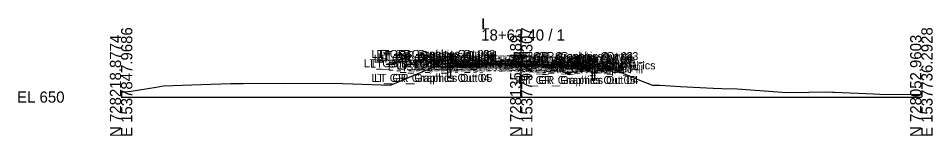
# Model space of a CAD drawing. Extents: x -26 to 1203, y -10 to 9522.
# Drawn here: x 974.3 to 1202.8, y -9.7 to 19.7 of the extents above; entities that cross this region are included whole.
import ezdxf

# ---------------------------------------------------------------- set-up
doc = ezdxf.new("R2010")
doc.units = 0
for name, color, linetype in [('Default', 7, 'Continuous'), ('Exist CMT Pavement', 7, 'Continuous'), ('Exist Cross Section Cell', 7, 'Continuous'), ('Exist XS Center Line Elevation Label', 7, 'Continuous'), ('Exist XS Ground Line', 7, 'Continuous'), ('Old_Level_63', 7, 'Continuous'), ('Prop CMT Guardrail Graphics', 7, 'Continuous'), ('Prop CMT Pvmt Course 1', 7, 'Continuous'), ('Prop CMT Pvmt Course 1 Wedge', 7, 'Continuous'), ('Prop CMT Pvmt Course 2 Wedge', 7, 'Continuous'), ('Prop CMT Pvmt Course 3', 7, 'Continuous'), ('Prop CMT Pvmt Surface', 7, 'Continuous'), ('Prop CMT Pvmt Surface Shoulder', 7, 'Continuous'), ('Prop CMT Pvmt Wedge Surface 1', 7, 'Continuous'), ('Prop CMT Pvmt Wedge Surface 2', 7, 'Continuous'), ('Prop CMT Pvmt Wedge Surface 3', 7, 'Continuous'), ('Prop CMT Shld Paved Course 1', 7, 'Continuous'), ('Prop CMT Shld Paved Course 2', 7, 'Continuous'), ('Prop CMT Shld Paved Course 3', 7, 'Continuous'), ('Prop CMT Slope Grass', 7, 'Continuous'), ('Prop CMT Subgrade Earthwork', 7, 'Continuous'), ('Prop Superelevation  Arrow CELL', 7, 'Continuous'), ('Prop XS EOT Tick Mark', 7, 'Continuous'), ('Prop XS SE Text', 7, 'Continuous'), ('Prop XS Side Slope Text', 7, 'Continuous')]:
    doc.layers.add(name, color=color, linetype=linetype)

msp = doc.modelspace()

# ---------------------------------------------------------------- linework, layer by layer
at = {"layer": 'Exist CMT Pavement'}
for points in [[(1100, 8.04), (1098.83, 8.04), (1094.75, 8.04), (1091.6, 8.04), (1090.66, 8.06), (1089.49, 8.08)], [(1100, 8.04), (1101.06, 8.04), (1101.22, 8.04), (1105.5, 7.93), (1109.35, 7.83), (1109.78, 7.82), (1111, 7.78)]]:
    msp.add_lwpolyline(points, dxfattribs=at)
at = {"layer": 'Exist Cross Section Cell'}
for p, q in [((1100, 0), (1100, 16.95)), ((1000, 0), (1100, 0)), ((1100, 0), (1200, 0))]:
    msp.add_line(p, q, dxfattribs=at)
at = {"layer": 'Exist XS Ground Line'}
msp.add_lwpolyline([(1000, 1.2), (1002.51, 1.52), (1008.74, 2.49), (1010.57, 2.78), (1022.45, 3.22), (1027.4, 3.4), (1030.47, 3.42), (1040.87, 3.48), (1055.34, 3.4), (1057.95, 3.32), (1067.32, 3), (1077.83, 7.38), (1078.04, 7.48), (1078.32, 7.5), (1087.4, 8.11), (1091.6, 8.04), (1100, 8.04), (1101.06, 8.04), (1109.35, 7.83), (1113.37, 7.7), (1117.2, 7.4), (1123.14, 6.93), (1130.37, 3.94), (1132.85, 3), (1134.61, 2.99), (1139.79, 2.62), (1147.95, 2.24), (1150.15, 2.14), (1153.93, 2.09), (1166.42, 1.14), (1177.39, 1.27), (1177.81, 1.25), (1178.25, 1.24), (1188.02, 0.82), (1189.59, 0.76), (1197.53, 0.67), (1200, 0.65)], dxfattribs=at)
at = {"layer": 'Prop CMT Guardrail Graphics'}
for points in [[(1081.63, 4.8), (1081.63, 10.8)], [(1081.63, 10.8), (1082.97, 10.8), (1083.24, 10.51)], [(1083.24, 9.93), (1082.97, 9.64), (1082.3, 9.64)], [(1082.3, 9.64), (1082.3, 4.8)], [(1083.24, 10.51), (1082.97, 10.22)], [(1082.97, 10.22), (1083.24, 9.93)], [(1118.37, 10.27), (1117.03, 10.27), (1116.76, 9.98)], [(1116.76, 9.98), (1117.03, 9.69)], [(1117.03, 9.69), (1116.76, 9.4)], [(1116.76, 9.4), (1117.03, 9.11), (1117.7, 9.11)], [(1118.37, 4.27), (1118.37, 10.27)], [(1117.7, 9.11), (1117.7, 4.27)], [(1082.3, 4.8), (1081.63, 4.8)], [(1117.7, 4.27), (1118.37, 4.27)]]:
    msp.add_lwpolyline(points, dxfattribs=at)
at = {"layer": 'Prop CMT Pvmt Course 1'}
for points in [[(1100, 8.37), (1089.49, 8.43)], [(1089.49, 8.43), (1089.49, 8.18), (1089.49, 8.18), (1089.49, 8.18)], [(1089.49, 8.18), (1100, 8.12)], [(1100, 8.12), (1100, 8.37)], [(1100, 8.37), (1111, 8.09)], [(1100, 8.12), (1100, 8.37)], [(1111, 7.84), (1100, 8.12)], [(1111, 8.09), (1111, 7.84), (1111, 7.84), (1111, 7.84)]]:
    msp.add_lwpolyline(points, dxfattribs=at)
at = {"layer": 'Prop CMT Pvmt Course 1 Wedge'}
for points in [[(1089.49, 8.18), (1091.6, 8.17), (1100, 8.12)], [(1089.49, 8.08), (1089.49, 8.18)], [(1100, 8.04), (1091.6, 8.04), (1089.49, 8.08)], [(1100, 8.12), (1100, 8.04)], [(1100, 8.12), (1101.06, 8.09), (1109.35, 7.88), (1111, 7.84)], [(1100, 8.04), (1100, 8.12)], [(1111, 7.78), (1109.35, 7.83), (1101.06, 8.04), (1100, 8.04)], [(1111, 7.84), (1111, 7.78)]]:
    msp.add_lwpolyline(points, dxfattribs=at)
at = {"layer": 'Prop CMT Pvmt Course 2 Wedge'}
for points in [[(1089.49, 8.18), (1091.6, 8.17), (1100, 8.12)], [(1089.49, 8.08), (1089.49, 8.18)], [(1100, 8.04), (1091.6, 8.04), (1089.49, 8.08)], [(1100, 8.12), (1100, 8.04)], [(1100, 8.12), (1101.06, 8.09), (1109.35, 7.88), (1111, 7.84)], [(1100, 8.04), (1100, 8.12)], [(1111, 7.78), (1109.35, 7.83), (1101.06, 8.04), (1100, 8.04)], [(1111, 7.84), (1111, 7.78)]]:
    msp.add_lwpolyline(points, dxfattribs=at)
at = {"layer": 'Prop CMT Pvmt Course 3'}
for points in [[(1089.49, 7.97), (1089.49, 7.97), (1089.49, 7.6), (1089.49, 7.6)], [(1089.49, 7.6), (1089.49, 7.97)], [(1111, 7.63), (1111, 7.63), (1111, 7.25), (1111, 7.25)], [(1111, 7.25), (1111, 7.63)]]:
    msp.add_lwpolyline(points, dxfattribs=at)
at = {"layer": 'Prop CMT Pvmt Surface'}
for points in [[(1100, 8.37), (1089.49, 8.43)], [(1100, 8.37), (1111, 8.09)]]:
    msp.add_lwpolyline(points, dxfattribs=at)
at = {"layer": 'Prop CMT Pvmt Surface Shoulder'}
for points in [[(1089.49, 8.43), (1083.25, 8.47)], [(1111, 8.09), (1116.75, 7.94)]]:
    msp.add_lwpolyline(points, dxfattribs=at)
at = {"layer": 'Prop CMT Pvmt Wedge Surface 1'}
for points in [[(1089.49, 8.18), (1089.49, 8.43)], [(1089.49, 8.43), (1089.49, 8.43)], [(1100, 8.12), (1089.49, 8.18)], [(1100, 8.12), (1111, 7.84)], [(1111, 7.84), (1111, 8.09)], [(1111, 8.09), (1111, 8.09)]]:
    msp.add_lwpolyline(points, dxfattribs=at)
at = {"layer": 'Prop CMT Pvmt Wedge Surface 2'}
for points in [[(1089.49, 8.18), (1089.49, 8.43)], [(1100, 8.12), (1089.49, 8.18)], [(1089.49, 8.18), (1089.49, 8.18)], [(1100, 8.12), (1111, 7.84)], [(1111, 7.84), (1111, 8.09)], [(1111, 7.84), (1111, 7.84)]]:
    msp.add_lwpolyline(points, dxfattribs=at)
at = {"layer": 'Prop CMT Pvmt Wedge Surface 3'}
for points in [[(1089.49, 7.97), (1089.49, 8.43)], [(1100, 7.91), (1089.49, 7.97)], [(1089.49, 7.97), (1089.49, 7.97)], [(1100, 7.91), (1111, 7.63)], [(1111, 7.63), (1111, 8.09)], [(1111, 7.63), (1111, 7.63)]]:
    msp.add_lwpolyline(points, dxfattribs=at)
at = {"layer": 'Prop CMT Shld Paved Course 1'}
for points in [[(1089.49, 8.43), (1083.25, 8.47), (1083, 8.22)], [(1083, 8.22), (1089.49, 8.18)], [(1089.49, 8.18), (1089.49, 8.43)], [(1111, 8.09), (1116.75, 7.94), (1117.01, 7.69)], [(1111, 7.84), (1111, 8.09)], [(1117.01, 7.69), (1111, 7.84)]]:
    msp.add_lwpolyline(points, dxfattribs=at)
at = {"layer": 'Prop CMT Shld Paved Course 2'}
for points in [[(1089.49, 8.18), (1083, 8.22), (1082.79, 8.01)], [(1082.79, 8.01), (1089.49, 7.97)], [(1089.49, 7.97), (1089.49, 8.18)], [(1111, 7.84), (1117.01, 7.69), (1117.22, 7.47)], [(1111, 7.63), (1111, 7.84)], [(1117.22, 7.47), (1111, 7.63)]]:
    msp.add_lwpolyline(points, dxfattribs=at)
at = {"layer": 'Prop CMT Shld Paved Course 3'}
for points in [[(1082.79, 8.01), (1082.42, 7.64)], [(1082.42, 7.64), (1089.49, 7.6)], [(1089.49, 7.97), (1082.79, 8.01)], [(1082.79, 8.01), (1082.79, 8.01)], [(1089.49, 7.6), (1089.49, 7.97)], [(1111, 7.63), (1117.22, 7.47)], [(1111, 7.25), (1111, 7.63)], [(1117.61, 7.09), (1111, 7.25)], [(1117.22, 7.47), (1117.22, 7.47)], [(1117.22, 7.47), (1117.61, 7.09)]]:
    msp.add_lwpolyline(points, dxfattribs=at)
at = {"layer": 'Prop CMT Slope Grass'}
for points in [[(1080.58, 8.33), (1078.04, 7.48)], [(1083.24, 8.47), (1080.58, 8.33)], [(1083.25, 8.47), (1083.24, 8.47)], [(1116.75, 7.94), (1116.76, 7.94)], [(1116.76, 7.94), (1119.42, 7.73)], [(1119.42, 7.73), (1123.14, 6.93)]]:
    msp.add_lwpolyline(points, dxfattribs=at)
at = {"layer": 'Prop CMT Subgrade Earthwork'}
for points in [[(1082.42, 7.64), (1081.67, 8.38)], [(1089.49, 7.6), (1082.42, 7.64)], [(1089.49, 7.6), (1089.49, 8.08)], [(1089.49, 7.6), (1089.49, 7.6)], [(1111, 7.25), (1111, 7.78)], [(1111, 7.25), (1117.61, 7.09)], [(1111, 7.25), (1111, 7.25)], [(1117.61, 7.09), (1118.33, 7.82)]]:
    msp.add_lwpolyline(points, dxfattribs=at)
at = {"layer": 'Prop Superelevation  Arrow CELL'}
for p, q in [((1092.29, 9.12), (1098.29, 9)), ((1103.22, 8.9), (1109.22, 8.78))]:
    msp.add_line(p, q, dxfattribs=at)
for points in [[(1098.29, 9), (1096.8, 9.53), (1097.13, 9.02)], [(1109.22, 8.78), (1107.73, 9.31), (1108.07, 8.8)]]:
    msp.add_lwpolyline(points, close=True, dxfattribs=at)
at = {"layer": 'Prop XS EOT Tick Mark'}
for points in [[(1089.49, 8.43), (1089.49, 9.43)], [(1111, 8.09), (1111, 9.09)]]:
    msp.add_lwpolyline(points, dxfattribs=at)

# ---------------------------------------------------------------- texts
at = {"layer": 'Default'}
msp.add_text('-', height=0.0001, dxfattribs=at).set_placement((1000, 0))
msp.add_text('-', height=0.0001, dxfattribs=at).set_placement((1000, 0))
msp.add_text('-', height=0.0001, dxfattribs=at).set_placement((1000, 0))
at = {"layer": 'Exist Cross Section Cell'}
for s, p in [('L', (1090, 16.95)), ('18+63.40 / 1', (1090, 14.15)), ('EL 650', (974, -1.4))]:
    msp.add_text(s, height=2.8, dxfattribs=at).set_placement(p)
for s, p in [('E 1537847.9686', (1002.8, -10)), ('E 1537792.1307', (1102.8, -10)), ('E 1537736.2928', (1202.8, -10)), ('N 728218.8774', (1000, -10)), ('N 728135.9189', (1100, -10)), ('N 728052.9603', (1200, -10))]:
    msp.add_text(s, height=2.8, rotation=90, dxfattribs=at).set_placement(p)
at = {"layer": 'Exist XS Center Line Elevation Label'}
msp.add_text('658.04', height=0.75, dxfattribs=at).set_placement((1098.51, 6.89))
at = {"layer": 'Old_Level_63'}
for s, p in [('LT_GR_Graphics Out 03', (1062.53, 9.8)), ('LT_GR_Graphics Out 02', (1063.86, 9.8)), ('LT_GR_Graphics Out 01', (1064.7, 9.51)), ('LT_GS_OS_GR_Face_Graphics', (1060.69, 7.47)), ('LT_Sub_Trench_Out_DLT', (1062.24, 7.38)), ('LT_GR_Graphics Out 06', (1063.15, 8.64)), ('LT_GR_Graphics Out 09', (1063.86, 9.22)), ('LT_GR_Graphics Out 07', (1063.86, 8.64)), ('LT_GR_Graphics Out 08', (1064.13, 8.93)), ('LT_GS_OS_CTL', (1069.95, 7.33)), ('LT_PS2_OEOP', (1073.23, 7.22)), ('LT_PS1_OEOP', (1074.05, 7.47)), ('LT_PV_Sub_Tie_Out', (1074.44, 7.08)), ('LT_PV1_OEEOP_Null', (1075.95, 7.43)), ('LT_PV1_OEEOP_W', (1077.47, 7.18)), ('LT_PV2_OEEOP', (1078.8, 7.18)), ('LT_PV2_OEOT', (1079.66, 7.18)), ('LT_PV1_OEOT', (1080.23, 7.43)), ('LT_TM_OEOT', (1080.44, 8.43)), ('PV2_PGL_W', (1092.02, 7.12)), ('PV1_PGL_W', (1092.58, 7.12)), ('PV1_PGL', (1094.47, 7.37)), ('RT_PV1_OEEOP_Null', (1097.41, 7.09)), ('RT_GR_Graphics Out 08', (1097.61, 8.4)), ('RT_GR_Graphics Out 02', (1097.88, 9.27)), ('RT_GR_Graphics Out 09', (1097.88, 8.69)), ('RT_GR_Graphics Out 07', (1097.88, 8.11)), ('RT_GR_Graphics Out 01', (1098.18, 8.98)), ('RT_GR_Graphics Out 06', (1098.5, 8.11)), ('RT_GR_Graphics Out 03', (1099.22, 9.27)), ('RT_TM_OEOT', (1101.9, 8.09)), ('LT_Sub_Trench_Out', (1066.62, 6.64)), ('LT_Slope_Fill', (1068.56, 6.48)), ('LT_PS3_Shelf_Out', (1068.78, 7.01)), ('LT_PS3_OEOP', (1073.03, 7.01)), ('LT_PV_EG_TestPt3', (1076.17, 7.06)), ('LT_PV_OEEOP_EG', (1077.04, 7.08)), ('LT_Sub_OEEOP', (1078.7, 6.6)), ('LT_PV3_OEEOP', (1078.8, 6.97)), ('LT_Sub_OEOT', (1079.57, 6.6)), ('LT_PV3_OEOT', (1079.66, 6.97)), ('LT_PV_EG_TestPt2', (1080.26, 7.04)), ('LT_PV_EG_TestPt1', (1084.91, 7.04)), ('RT_PV_EG_TestPt1', (1087.25, 7.04)), ('RT_PV_EG_TestPt2', (1090.96, 6.93)), ('PV_EPGL_EG', (1091.24, 7.04)), ('PV3_PGL_W', (1092.02, 6.91)), ('RT_GS_OS_GR_Face_Graphics', (1094.17, 6.94)), ('RT_PV_EG_TestPt3', (1095.24, 6.82)), ('RT_PV_Sub_Tie_Out', (1095.9, 6.78)), ('RT_PV_OEEOP_EG', (1098.49, 6.78)), ('RT_Sub_Trench_Out_DLT', (1098.85, 6.82)), ('RT_PV1_OEEOP_W', (1098.94, 6.84)), ('RT_Sub_OEEOP', (1100.17, 6.25)), ('RT_PV2_OEEOP', (1100.26, 6.84)), ('RT_PV3_OEEOP', (1100.26, 6.63)), ('RT_Sub_OEOT', (1101.03, 6.25)), ('RT_PV2_OEOT', (1101.13, 6.84)), ('RT_PV3_OEOT', (1101.13, 6.63)), ('RT_PV1_OEOT', (1101.69, 7.09)), ('RT_Sub_Trench_Out', (1101.76, 6.09)), ('RT_PS3_Shelf_Out', (1103.16, 6.47)), ('RT_PS2_OEOP', (1107.2, 6.69)), ('RT_PS3_OEOP', (1107.41, 6.47)), ('RT_PS1_OEOP', (1107.51, 6.94)), ('RT_GS_OS_CTL', (1108.75, 6.73)), ('RT_Slope_Fill', (1113.62, 5.93)), ('LT_GR_Graphics Out 04', (1062.53, 3.8)), ('LT_GR_Graphics Out 05', (1063.2, 3.8)), ('RT_GR_Graphics Out 05', (1098.55, 3.27)), ('RT_GR_Graphics Out 04', (1099.22, 3.27))]:
    msp.add_text(s, height=2, dxfattribs=at).set_placement(p)
at = {"layer": 'Prop XS SE Text'}
for s, rotation, p in [('0.006', 359.6485, (1093.01, 9.41)), ('0.025', 358.5473, (1103.79, 9.27))]:
    msp.add_text(s, height=1, rotation=rotation, dxfattribs=at).set_placement(p)
at = {"layer": 'Prop XS Side Slope Text'}
for s, rotation, p in [('3.01:1', 18.4023, (1077.5, 8.09)), ('4.65:1', 347.8661, (1119.7, 8.44))]:
    msp.add_text(s, height=1, rotation=rotation, dxfattribs=at).set_placement(p)

doc.saveas('drawing.dxf')
